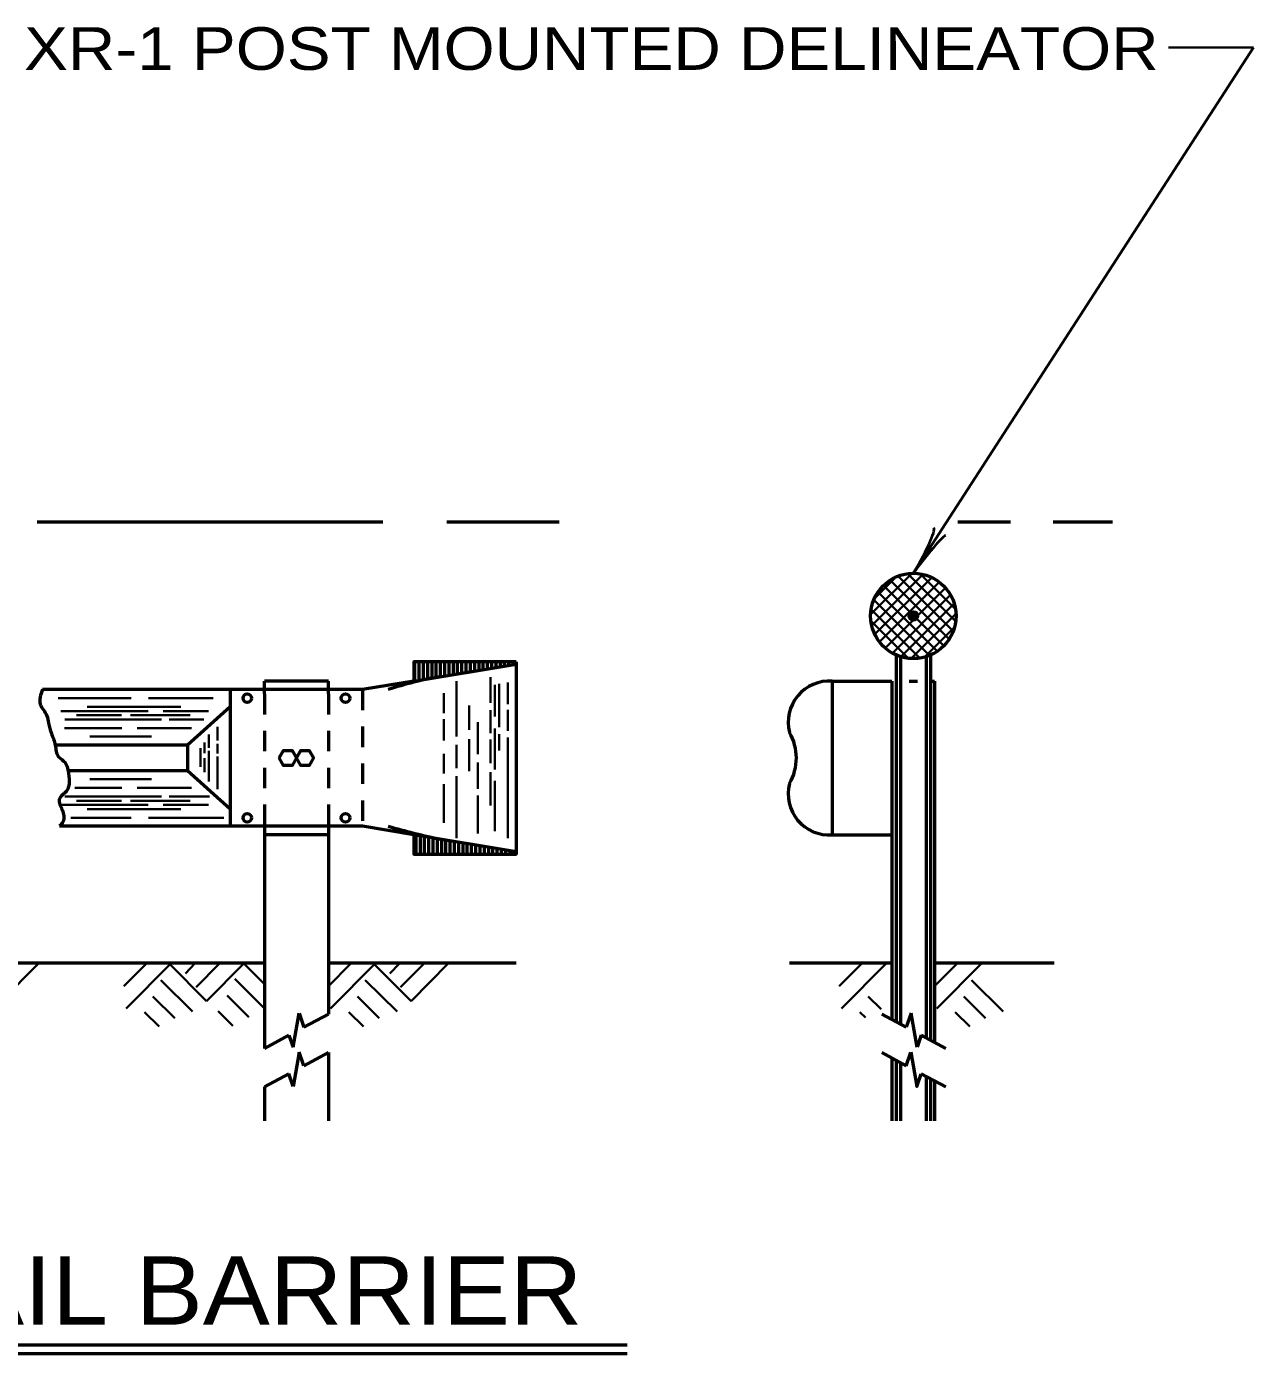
# Model space of a CAD drawing. Extents: x -60 to 620, y -42 to 398.
# Drawn here: x 264.3 to 336.2, y 75.7 to 153.4 of the extents above; entities that cross this region are included whole.
import ezdxf
from ezdxf.enums import TextEntityAlignment as Align

# ---------------------------------------------------------------- set-up
doc = ezdxf.new("R2010")
doc.units = 0
doc.header["$LTSCALE"] = 0.8
doc.linetypes.add('SHORT_DASHED', pattern=[2.7, 1.5, -1.2])
doc.layers.add('1', color=7, linetype='Continuous', lineweight=35)

msp = doc.modelspace()

# ---------------------------------------------------------------- hatches: boundary and pattern name
at = {"layer": '1'}
msp.add_hatch(color=256, dxfattribs=at).paths.add_polyline_path([(316.5157, 118.8916, 1), (316.0157, 118.8916, 1)])

# ---------------------------------------------------------------- linework, layer by layer
for p, q in [((316.2657, 121.3916), (336.1825, 152.1655)), ((331.1998, 152.1655), (336.1825, 152.1655)), ((313.7726, 118.9902), (316.1681, 121.3857)), ((313.8317, 118.3422), (316.8152, 121.3258)), ((318.6017, 118.0098), (315.3847, 121.227)), ((318.7413, 118.5773), (315.9518, 121.3669)), ((318.7283, 119.2976), (316.6694, 121.3564)), ((313.9902, 119.9149), (315.2448, 121.1695)), ((314.0135, 117.8169), (317.3423, 121.1457)), ((314.2786, 117.3749), (317.7797, 120.8761)), ((318.0499, 117.1475), (314.5216, 120.6758)), ((314.6237, 117.0129), (318.1447, 120.5339)), ((318.3653, 117.5392), (314.9122, 120.9922)), ((317.2043, 116.5789), (313.9524, 119.8307)), ((317.6676, 116.8227), (314.1977, 120.2926)), ((315.0361, 116.7182), (318.4402, 120.1223)), ((316.6497, 116.4263), (313.8002, 119.2759)), ((315.5296, 116.5046), (318.6507, 119.6257)), ((316.1303, 116.3982), (318.7572, 119.0251)), ((315.954, 116.4149), (313.788, 118.5809)), ((316.9237, 116.4845), (318.6722, 118.233)), ((314.7699, 116.8919), (314.2617, 117.4002)), ((289.5138, 115.0682), (289.5138, 111.8383)), ((291.5138, 115.3034), (291.5138, 113.8139)), ((292.5138, 114.9928), (292.5138, 113.7198)), ((288.7638, 114.3661), (288.7638, 113.2024)), ((291.7638, 114.8678), (291.7638, 113.0142)), ((292.0138, 114.9095), (292.0138, 112.3714)), ((270.472, 114.0762), (266.1895, 114.0762)), ((273.3773, 113.5762), (267.8931, 113.5762)), ((275.2638, 114.0762), (271.4825, 114.0762)), ((290.2638, 113.6414), (290.2638, 112.2302)), ((271.4615, 113.3262), (266.35, 113.3262)), ((272.2404, 112.8262), (266.5749, 112.8262)), ((269.9036, 113.0762), (267.2615, 113.0762)), ((273.9246, 113.0762), (270.4299, 113.0762)), ((274.9861, 113.3262), (272.3352, 113.3262)), ((274.7141, 112.8262), (272.6931, 112.8262)), ((288.7638, 112.8417), (288.7638, 111.6031)), ((290.7638, 112.6692), (290.7638, 110.8034)), ((291.5138, 113.3748), (291.5138, 112.0264)), ((292.5138, 113.3905), (292.5138, 112.1676)), ((269.9247, 112.3262), (266.5668, 112.3262)), ((273.9983, 112.3262), (270.8194, 112.3262)), ((275.0138, 111.9512), (275.0138, 111.1667)), ((275.5138, 112.4012), (275.5138, 111.5919)), ((291.7638, 112.3087), (291.7638, 109.8941)), ((292.0138, 111.9637), (292.0138, 111.0072)), ((271.6509, 111.8262), (268.051, 111.8262)), ((274.5138, 111.146), (274.5138, 110.0675)), ((274.7638, 111.4778), (274.7638, 110.866)), ((275.5138, 111.4052), (275.5138, 110.8452)), ((289.5138, 111.3366), (289.5138, 109.9724)), ((290.2638, 111.6815), (290.2638, 109.8)), ((291.5138, 111.6502), (291.5138, 110.2703)), ((292.5138, 111.7756), (292.5138, 105.8802)), ((274.7638, 110.5652), (274.7638, 109.7461)), ((275.0138, 111.0008), (275.0138, 109.2012)), ((275.5138, 110.6586), (275.5138, 108.7512)), ((288.7638, 110.8192), (288.7638, 109.6588)), ((290.7638, 110.3174), (290.7638, 108.7652)), ((291.5138, 109.7529), (291.5138, 107.793)), ((269.9247, 108.8262), (267.1667, 108.8262)), ((271.6509, 109.3262), (268.051, 109.3262)), ((273.9983, 108.8262), (270.8194, 108.8262)), ((288.7638, 109.0474), (288.7638, 106.7844)), ((289.5138, 109.5021), (289.5138, 105.8802)), ((291.7638, 109.2355), (291.7638, 106.2845)), ((272.2404, 108.3262), (266.5749, 108.3262)), ((269.9036, 108.0762), (267.2615, 108.0762)), ((273.9246, 108.0762), (270.4299, 108.0762)), ((275.0404, 108.3262), (272.6931, 108.3262)), ((290.7638, 108.3732), (290.7638, 106.1467)), ((271.4615, 107.8262), (266.35, 107.8262)), ((273.3773, 107.5762), (267.8931, 107.5762)), ((274.9861, 107.8262), (272.3352, 107.8262)), ((270.472, 107.0762), (266.9352, 107.0762)), ((275.893, 107.0762), (271.4825, 107.0762)), ((265.0338, 98.5362), (262.8538, 96.3362)), ((271.3605, 98.5362), (270.0405, 97.2162)), ((272.7805, 98.5362), (270.1605, 95.9162)), ((272.6805, 98.5362), (274.8805, 96.3362)), ((274.2005, 98.5362), (273.6405, 97.9562)), ((275.6405, 98.5362), (274.2605, 97.1562)), ((277.0605, 98.5362), (274.8805, 96.3362)), ((277.0605, 98.5362), (278.2638, 97.3328)), ((283.3338, 98.5362), (282.0138, 97.2162)), ((284.7538, 98.5362), (282.1338, 95.9162)), ((284.6538, 98.5362), (286.8538, 96.3362)), ((286.1738, 98.5362), (285.6138, 97.9562)), ((287.6138, 98.5362), (286.2338, 97.1562)), ((289.0338, 98.5362), (286.8538, 96.3362)), ((313.2493, 98.5362), (311.9292, 97.2162)), ((314.6692, 98.5362), (312.0492, 95.9162)), ((318.8338, 98.5362), (317.5138, 97.2162)), ((320.2538, 98.5362), (317.6338, 95.9162)), ((272.2005, 97.5762), (274.0605, 95.7362)), ((276.5405, 97.6362), (278.2638, 95.9128)), ((284.1738, 97.5762), (286.0338, 95.7362)), ((319.6738, 97.5762), (321.5338, 95.7362)), ((271.7405, 96.6162), (273.0205, 95.3362)), ((276.0805, 96.6762), (277.3605, 95.3962)), ((283.7138, 96.6162), (284.9938, 95.3362)), ((313.6293, 96.6162), (314.374, 95.8714)), ((319.2138, 96.6162), (320.4938, 95.3362)), ((271.2405, 95.6962), (272.1005, 94.8562)), ((275.5605, 95.7562), (276.4205, 94.8962)), ((283.2138, 95.6962), (284.0738, 94.8562)), ((313.1293, 95.6962), (313.4559, 95.3771)), ((318.7138, 95.6962), (319.5738, 94.8562))]:
    msp.add_line(p, q, dxfattribs=at)
at = {"layer": '1', "lineweight": 53}
for p, q in [((264.9572, 124.3998), (277.8464, 124.3998)), ((276.9839, 124.3998), (285.2072, 124.3998)), ((288.9572, 124.3998), (295.5288, 124.3998)), ((318.8727, 124.3998), (321.9572, 124.3998)), ((324.4572, 124.3998), (327.9203, 124.3998)), ((315.2638, 116.6011), (315.2638, 95.1232)), ((317.2638, 116.5995), (317.2638, 94.0565)), ((287.0817, 115.0875), (287.0817, 116.2012)), ((287.3317, 115.1292), (287.3317, 116.2012)), ((287.5817, 115.1708), (287.5817, 116.2012)), ((287.8317, 115.2125), (287.8317, 116.2012)), ((288.0817, 115.2542), (288.0817, 116.2012)), ((288.3317, 115.2958), (288.3317, 116.2012)), ((288.5817, 115.3375), (288.5817, 116.2012)), ((288.8317, 115.3792), (288.8317, 116.2012)), ((289.0817, 115.4208), (289.0817, 116.2012)), ((289.3317, 115.4625), (289.3317, 116.2012)), ((289.5817, 115.5042), (289.5817, 116.2012)), ((289.8317, 115.5458), (289.8317, 116.2012)), ((290.0817, 115.5875), (290.0817, 116.2012)), ((290.3317, 115.6292), (290.3317, 116.2012)), ((290.5817, 115.6708), (290.5817, 116.2012)), ((290.8317, 115.7125), (290.8317, 116.2012)), ((291.0817, 115.7542), (291.0817, 116.2012)), ((291.3317, 115.7958), (291.3317, 116.2012)), ((291.5817, 115.8375), (291.5817, 116.2012)), ((291.8317, 115.8792), (291.8317, 116.2012)), ((292.0817, 115.9208), (292.0817, 116.2012)), ((292.3317, 115.9625), (292.3317, 116.2012)), ((292.5817, 116.0042), (292.5817, 116.2012)), ((292.8317, 116.0458), (292.8317, 116.2012)), ((293.0138, 116.2012), (293.0138, 104.9512)), ((315.5138, 116.5073), (315.5138, 94.9898)), ((317.0138, 116.5062), (317.0138, 94.1898)), ((278.2638, 114.3262), (278.2638, 115.0762)), ((282.0138, 115.0762), (278.2638, 115.0762)), ((282.0138, 114.3262), (282.0138, 115.0762)), ((287.0138, 115.0763), (284.0138, 114.5762)), ((311.5138, 115.0762), (311.5138, 106.0762)), ((311.5138, 115.0762), (315.0138, 115.0762)), ((315.0138, 115.0762), (315.0138, 95.2565)), ((316.0138, 115.0762), (316.5138, 115.0762)), ((317.2638, 115.0762), (317.5138, 115.0762)), ((317.5138, 115.0762), (317.5138, 93.9232)), ((284.0138, 114.5762), (265.2638, 114.5762)), ((276.2638, 114.5762), (276.2638, 106.5762)), ((276.2638, 113.5762), (273.7638, 111.3262)), ((273.7638, 111.3262), (266.0138, 111.3262)), ((273.7638, 111.3262), (273.7638, 109.8262)), ((273.7638, 109.8262), (266.7638, 109.8262)), ((276.2638, 107.5762), (273.7638, 109.8262)), ((278.2638, 106.8262), (278.2638, 93.5762)), ((282.0138, 106.8262), (282.0138, 95.5762)), ((287.0138, 106.0762), (284.0138, 106.5762)), ((282.0138, 106.0762), (278.2638, 106.0762)), ((293.0138, 105.0762), (287.0138, 106.0761)), ((287.1475, 104.9512), (287.1475, 106.0538)), ((287.3975, 104.9512), (287.3975, 106.0122)), ((287.6475, 104.9512), (287.6475, 105.9705)), ((287.8975, 104.9512), (287.8975, 105.9288)), ((288.1475, 104.9512), (288.1475, 105.8872)), ((288.3975, 104.9512), (288.3975, 105.8455)), ((288.6475, 104.9512), (288.6475, 105.8038)), ((288.8975, 104.9512), (288.8975, 105.7622)), ((289.1475, 104.9512), (289.1475, 105.7205)), ((289.3975, 104.9512), (289.3975, 105.6788)), ((311.5138, 106.0762), (315.0138, 106.0762)), ((289.6475, 104.9512), (289.6475, 105.6372)), ((289.8975, 104.9512), (289.8975, 105.5955)), ((290.1475, 104.9512), (290.1475, 105.5538)), ((290.3975, 104.9512), (290.3975, 105.5122)), ((290.6475, 104.9512), (290.6475, 105.4705)), ((290.8975, 104.9512), (290.8975, 105.4288)), ((291.1475, 104.9512), (291.1475, 105.3872)), ((291.3975, 104.9512), (291.3975, 105.3455)), ((291.6475, 104.9512), (291.6475, 105.3038)), ((291.8975, 104.9512), (291.8975, 105.2622)), ((292.1475, 104.9512), (292.1475, 105.2206)), ((292.3975, 104.9512), (292.3975, 105.1789)), ((292.6475, 104.9512), (292.6475, 105.1372)), ((292.8975, 104.9512), (292.8975, 105.0956)), ((258.0138, 98.5762), (278.2638, 98.5762)), ((282.0138, 98.5762), (293.0138, 98.5762)), ((309.0138, 98.5762), (315.0138, 98.5762)), ((317.5138, 98.5762), (324.5138, 98.5762)), ((279.9428, 93.638), (280.2942, 95.6307)), ((280.2942, 95.6307), (280.5801, 94.8114)), ((282.0138, 95.5762), (280.5801, 94.8114)), ((314.4146, 95.5762), (315.8483, 94.8114)), ((316.1342, 95.6307), (315.8483, 94.8114)), ((316.4856, 93.638), (316.1342, 95.6307)), ((279.6977, 94.3408), (278.2638, 93.5762)), ((279.6977, 94.3408), (279.9428, 93.638)), ((316.7308, 94.3408), (316.4856, 93.638)), ((316.7308, 94.3408), (318.1646, 93.5762)), ((280.3075, 93.3427), (279.9561, 91.35)), ((280.58, 92.5615), (280.3075, 93.3427)), ((280.58, 92.5615), (282.0138, 93.3262)), ((282.0138, 93.3262), (282.0138, 89.3262)), ((315.8484, 92.5615), (314.4146, 93.3262)), ((315.8484, 92.5615), (316.1209, 93.3427)), ((315.0138, 93.0066), (315.0138, 89.3262)), ((315.2638, 92.8732), (315.2638, 89.3262)), ((315.5138, 92.7399), (315.5138, 89.3262)), ((278.2638, 91.3262), (279.6976, 92.0909)), ((279.9561, 91.35), (279.6976, 92.0909)), ((318.1646, 91.3262), (316.7308, 92.0909)), ((317.0138, 91.94), (317.0138, 89.3262)), ((317.2638, 91.8066), (317.2638, 89.3262)), ((317.5138, 91.6732), (317.5138, 89.3262)), ((278.2638, 91.3262), (278.2638, 89.3262)), ((194.8453, 76.2125), (299.5077, 76.2125)), ((194.8453, 75.7125), (299.5077, 75.7125))]:
    msp.add_line(p, q, dxfattribs=at)
at = {"layer": '1', "linetype": 'SHORT_DASHED', "lineweight": 53}
for p, q in [((278.2638, 114.3262), (278.2638, 106.8262)), ((282.0138, 114.3262), (282.0138, 106.8262)), ((284.0138, 114.5762), (284.0138, 106.5762))]:
    msp.add_line(p, q, dxfattribs=at)
at = {"layer": '1', "lineweight": 53}
for points in [[(293.0138, 116.2012), (287.0138, 116.2012), (287.0138, 115.0762), (293.0138, 116.0762)], [(279.1388, 110.5762), (279.3888, 111.0092), (279.8888, 111.0092), (280.1388, 110.5762), (279.8888, 110.1432), (279.3888, 110.1432)], [(280.1388, 110.5762), (280.3888, 111.0092), (280.8888, 111.0092), (281.1388, 110.5762), (280.8888, 110.1432), (280.3888, 110.1432)]]:
    msp.add_lwpolyline(points, close=True, dxfattribs=at)
for points in [[(284.0138, 106.5762), (282.0138, 106.5762), (278.2638, 106.5762), (266.2638, 106.5762)], [(287.0138, 106.0762), (287.0138, 104.9512), (293.0138, 104.9512), (293.0138, 105.0762)], [(316.1209, 93.3427), (316.4723, 91.35), (316.7308, 92.0909)]]:
    msp.add_lwpolyline(points, dxfattribs=at)
for centre, radius in [((316.2657, 118.8916), 2.5), ((316.2657, 118.8916), 0.25), ((277.2638, 114.0762), 0.25), ((283.0138, 114.0762), 0.25), ((277.2638, 107.0762), 0.25), ((283.0138, 107.0762), 0.25)]:
    msp.add_circle(centre, radius, dxfattribs=at)
for centre, radius, start, end in [((291.6928, 96.2354), 19.3536, 99.45399, 108.6185), ((311.3564, 112.6657), 2.4156, 86.26433, 194.12453), ((306.4226, 110.5762), 2.9941, 329.93454, 30.06547), ((311.3343, 108.4682), 2.3988, 165.3192, 274.29194), ((301.504, 164.1618), 59.7645, 254.48129, 257.44622)]:
    msp.add_arc(centre, radius, start, end, dxfattribs=at)
at = {"layer": '1', "lineweight": 40}
for centre, major_axis, ratio, start_param, end_param in [((316.6266, 122.4578), (-0.8391, -1.584), 0.122415, 0.8963533, 3.1415927), ((317.0521, 122.2173), (1.1018, 1.3791), 0.07063, 6.2823074, 8.5597026)]:
    msp.add_ellipse(centre, major_axis=major_axis, ratio=ratio, start_param=start_param, end_param=end_param, dxfattribs=at)
at = {"layer": '1', "lineweight": 53}
msp.add_spline([(265.2638, 114.5762), (265.1382, 113.7309), (265.5264, 113.0512), (265.6235, 112.6143), (265.7933, 112.0075), (266.0138, 111.3262), (266.2058, 110.6482), (266.5941, 110.3083), (266.7638, 109.8262), (266.6669, 108.6334), (266.2544, 108.148), (266.4242, 107.5412), (266.4728, 106.8615), (266.2638, 106.5762)], degree=3, dxfattribs=at)

# ---------------------------------------------------------------- texts
at = {"layer": '1', "width": 1.15}
msp.add_text('ALTERNATE XR-1 POST MOUNTED DELINEATOR', height=2.5, dxfattribs=at).set_placement((285.5537, 150.8628), align=Align.CENTER)
at = {"layer": '1', "width": 1.1}
msp.add_text('TEMPORARY GUARDRAIL BARRIER', height=4, dxfattribs=at).set_placement((195.8659, 77.3969))

doc.saveas('drawing.dxf')
